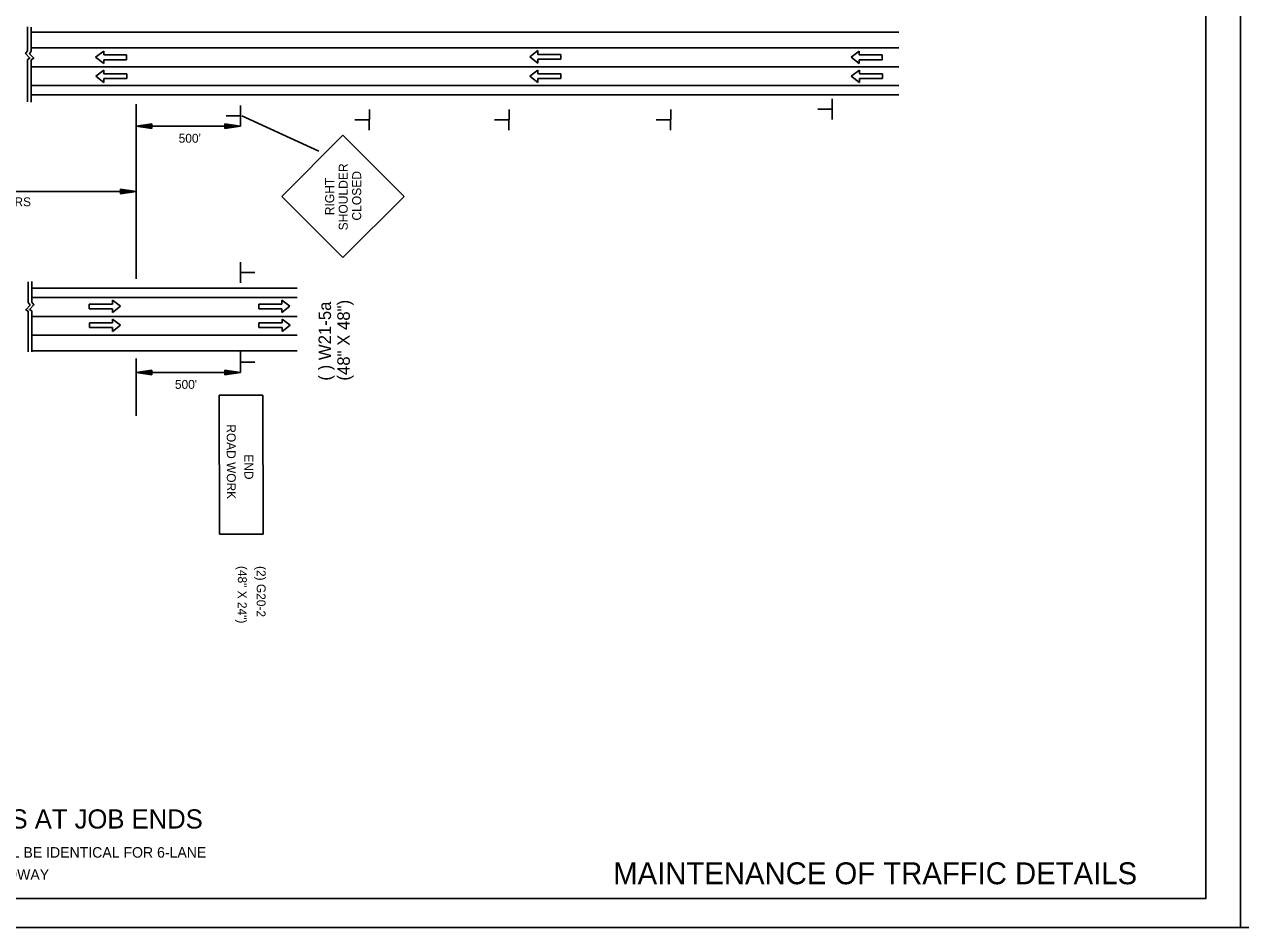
# Model space of a CAD drawing. Extents: x 1397271 to 1411271, y 376395 to 377888.
# Drawn here: x 1398438 to 1399604, y 376395 to 377260 of the extents above; entities that cross this region are included whole.
import ezdxf

# ---------------------------------------------------------------- set-up
doc = ezdxf.new("R2010")
doc.units = 0
for name, color, linetype in [('Default', 7, 'Continuous'), ('R_Border', 7, 'Continuous'), ('R_Draft', 7, 'Continuous'), ('R_MOT', 7, 'Continuous'), ('R_No Plot', 7, 'Continuous')]:
    doc.layers.add(name, color=color, linetype=linetype)

msp = doc.modelspace()

# ---------------------------------------------------------------- linework, layer by layer
at = {"layer": 'Default'}
for p, q in [((1398440.9, 377258), (1398440.9, 377235)), ((1398444.5, 377257.7), (1398444.5, 377234.7)), ((1399276.4, 377252.8), (1398445.2, 377252.8)), ((1399276.4, 377237.8), (1398445.2, 377237.8)), ((1398506.2, 377228.8), (1398514, 377234.8)), ((1398514, 377231), (1398514, 377234.8)), ((1398514, 377231), (1398536, 377231)), ((1398536, 377226.5), (1398536, 377231)), ((1398922.5, 377229.2), (1398930.2, 377235.2)), ((1398930.2, 377231.4), (1398930.2, 377235.2)), ((1398930.2, 377231.4), (1398952.3, 377231.4)), ((1398952.3, 377226.9), (1398952.3, 377231.4)), ((1399230.8, 377228.8), (1399238.5, 377234.8)), ((1399238.5, 377231), (1399238.5, 377234.8)), ((1399238.5, 377231), (1399260.6, 377231)), ((1399260.6, 377226.5), (1399260.6, 377231)), ((1398440.9, 377226.7), (1398440.9, 377186.1)), ((1398444.5, 377226.5), (1398444.5, 377185.9)), ((1399276.4, 377219.8), (1398445.2, 377219.8)), ((1398514, 377222.8), (1398506.2, 377228.8)), ((1398514, 377226.5), (1398536, 377226.5)), ((1398514, 377222.8), (1398514, 377226.5)), ((1398930.2, 377223.2), (1398922.5, 377229.2)), ((1398930.2, 377226.9), (1398952.3, 377226.9)), ((1398930.2, 377223.2), (1398930.2, 377226.9)), ((1399238.5, 377222.8), (1399230.8, 377228.8)), ((1399238.5, 377226.5), (1399260.6, 377226.5)), ((1399238.5, 377222.8), (1399238.5, 377226.5)), ((1398506.3, 377210.6), (1398514.1, 377216.6)), ((1398514.1, 377204.6), (1398506.3, 377210.6)), ((1398514.1, 377212.9), (1398514.1, 377216.6)), ((1398514.1, 377212.9), (1398536.1, 377212.9)), ((1398514.1, 377208.4), (1398536.1, 377208.4)), ((1398514.1, 377204.6), (1398514.1, 377208.4)), ((1398536.1, 377208.4), (1398536.1, 377212.9)), ((1398922.6, 377210.6), (1398930.4, 377216.6)), ((1398930.4, 377204.6), (1398922.6, 377210.6)), ((1398930.4, 377212.9), (1398930.4, 377216.6)), ((1398930.4, 377212.9), (1398952.4, 377212.9)), ((1398930.4, 377208.4), (1398952.4, 377208.4)), ((1398930.4, 377204.6), (1398930.4, 377208.4)), ((1398952.4, 377208.4), (1398952.4, 377212.9)), ((1399230.9, 377210.6), (1399238.7, 377216.6)), ((1399238.7, 377204.6), (1399230.9, 377210.6)), ((1399238.7, 377212.9), (1399238.7, 377216.6)), ((1399238.7, 377212.9), (1399260.7, 377212.9)), ((1399238.7, 377208.4), (1399260.7, 377208.4)), ((1399238.7, 377204.6), (1399238.7, 377208.4)), ((1399260.7, 377208.4), (1399260.7, 377212.9)), ((1399276.4, 377201.8), (1398445.2, 377201.8)), ((1399276.4, 377192.8), (1398445.2, 377192.8)), ((1398545.2, 377016.5), (1398545.2, 377183.8)), ((1398646.3, 377172.8), (1398720.3, 377138.8)), ((1398645.2, 377162.9), (1398545.2, 377162.9)), ((1398218.1, 377100.1), (1398545.2, 377100.1)), ((1398441.5, 377013.6), (1398441.5, 376993.7)), ((1398445.2, 377013.9), (1398445.2, 376994)), ((1398699.5, 377007.5), (1398445.2, 377007.5)), ((1398699.5, 376998.5), (1398445.2, 376998.5)), ((1398441.5, 376985.5), (1398441.5, 376946.4)), ((1398445.2, 376985.7), (1398445.2, 376946.4)), ((1398522.3, 376992.3), (1398500.2, 376992.3)), ((1398500.2, 376992.3), (1398500.2, 376987.8)), ((1398522.3, 376987.8), (1398500.2, 376987.8)), ((1398522.3, 376996.1), (1398522.3, 376992.3)), ((1398522.3, 376996.1), (1398530.1, 376990.1)), ((1398530.1, 376990.1), (1398522.3, 376984.1)), ((1398522.3, 376987.8), (1398522.3, 376984.1)), ((1398684.8, 376992.3), (1398662.8, 376992.3)), ((1398662.8, 376992.3), (1398662.8, 376987.8)), ((1398684.8, 376987.8), (1398662.8, 376987.8)), ((1398684.8, 376996.1), (1398684.8, 376992.3)), ((1398684.8, 376996.1), (1398692.6, 376990.1)), ((1398692.6, 376990.1), (1398684.8, 376984.1)), ((1398684.8, 376987.8), (1398684.8, 376984.1)), ((1398699.5, 376980.5), (1398445.2, 376980.5)), ((1398522.4, 376974.2), (1398500.3, 376974.2)), ((1398500.3, 376974.2), (1398500.3, 376969.7)), ((1398522.4, 376977.9), (1398522.4, 376974.2)), ((1398522.4, 376977.9), (1398530.2, 376971.9)), ((1398685, 376974.2), (1398662.9, 376974.2)), ((1398662.9, 376974.2), (1398662.9, 376969.7)), ((1398685, 376977.9), (1398685, 376974.2)), ((1398685, 376977.9), (1398692.7, 376971.9)), ((1398699.5, 376962.5), (1398445.2, 376962.5)), ((1398522.4, 376969.7), (1398500.3, 376969.7)), ((1398530.2, 376971.9), (1398522.4, 376965.9)), ((1398522.4, 376969.7), (1398522.4, 376965.9)), ((1398685, 376969.7), (1398662.9, 376969.7)), ((1398692.7, 376971.9), (1398685, 376965.9)), ((1398685, 376969.7), (1398685, 376965.9)), ((1398699.5, 376947.5), (1398445.2, 376947.5)), ((1398545.2, 376940.1), (1398545.2, 376885.1)), ((1398645.2, 376926.6), (1398545.2, 376926.6))]:
    msp.add_line(p, q, dxfattribs=at)
for points in [[(1398440.9, 377226.7), (1398443.2, 377228.1), (1398439.1, 377232.4), (1398440.9, 377235)], [(1398444.5, 377226.5), (1398446.9, 377227.9), (1398442.7, 377232.1), (1398444.5, 377234.7)], [(1398441.5, 376985.5), (1398439.2, 376986.9), (1398443.4, 376991.1), (1398441.5, 376993.7)], [(1398445.2, 376985.7), (1398442.8, 376987.1), (1398447, 376991.4), (1398445.2, 376994)]]:
    msp.add_lwpolyline(points, dxfattribs=at)
at = {"layer": 'R_Border'}
for q in [(1399571, 377860.7), (1397357.7, 376422.5)]:
    msp.add_line((1399571, 376422.5), q, dxfattribs=at)
at = {"layer": 'R_Draft'}
for p, q in [((1398560.2, 377165.1), (1398545.2, 377162.9)), ((1398560.2, 377160.6), (1398545.2, 377162.9)), ((1398560.2, 377164.8), (1398547.7, 377162.9)), ((1398560.2, 377161), (1398547.7, 377162.9)), ((1398560.2, 377164.4), (1398550.3, 377162.9)), ((1398560.2, 377161.4), (1398550.3, 377162.9)), ((1398560.2, 377164), (1398552.8, 377162.9)), ((1398560.2, 377161.8), (1398552.8, 377162.9)), ((1398560.2, 377163.6), (1398555.3, 377162.9)), ((1398560.2, 377162.2), (1398555.3, 377162.9)), ((1398560.2, 377163.2), (1398557.8, 377162.9)), ((1398560.2, 377162.5), (1398557.8, 377162.9)), ((1398560.2, 377160.6), (1398560.2, 377165.1)), ((1398630.2, 377165.1), (1398645.2, 377162.9)), ((1398630.2, 377165.1), (1398630.2, 377160.6)), ((1398630.2, 377164.8), (1398642.7, 377162.9)), ((1398630.2, 377164.4), (1398640.1, 377162.9)), ((1398630.2, 377164), (1398637.6, 377162.9)), ((1398630.2, 377163.6), (1398635.1, 377162.9)), ((1398630.2, 377163.2), (1398632.5, 377162.9)), ((1398630.2, 377160.6), (1398645.2, 377162.9)), ((1398630.2, 377162.2), (1398635.1, 377162.9)), ((1398630.2, 377161.4), (1398640.1, 377162.9)), ((1398630.2, 377161), (1398642.7, 377162.9)), ((1398630.2, 377161.8), (1398637.6, 377162.9)), ((1398630.2, 377162.5), (1398632.5, 377162.9)), ((1398530.2, 377102.4), (1398545.2, 377100.1)), ((1398530.2, 377102.4), (1398530.2, 377097.9)), ((1398530.2, 377102), (1398542.6, 377100.1)), ((1398530.2, 377101.6), (1398540.1, 377100.1)), ((1398530.2, 377101.3), (1398537.6, 377100.1)), ((1398530.2, 377100.9), (1398535, 377100.1)), ((1398530.2, 377100.5), (1398532.5, 377100.1)), ((1398530.2, 377097.9), (1398545.2, 377100.1)), ((1398530.2, 377099.4), (1398535, 377100.1)), ((1398530.2, 377098.6), (1398540.1, 377100.1)), ((1398530.2, 377098.3), (1398542.6, 377100.1)), ((1398530.2, 377099), (1398537.6, 377100.1)), ((1398530.2, 377099.8), (1398532.5, 377100.1)), ((1398560.2, 376928.8), (1398545.2, 376926.6)), ((1398560.2, 376928.5), (1398547.7, 376926.6)), ((1398560.2, 376928.1), (1398550.2, 376926.6)), ((1398560.2, 376927.7), (1398552.7, 376926.6)), ((1398560.2, 376927.3), (1398555.3, 376926.6)), ((1398560.2, 376924.3), (1398560.2, 376928.8)), ((1398630.2, 376928.8), (1398645.2, 376926.6)), ((1398630.2, 376928.8), (1398630.2, 376924.3)), ((1398630.2, 376928.5), (1398642.7, 376926.6)), ((1398630.2, 376928.1), (1398640.1, 376926.6)), ((1398630.2, 376927.7), (1398637.6, 376926.6)), ((1398630.2, 376927.3), (1398635, 376926.6)), ((1398560.2, 376924.3), (1398545.2, 376926.6)), ((1398560.2, 376924.7), (1398547.7, 376926.6)), ((1398560.2, 376925.1), (1398550.2, 376926.6)), ((1398560.2, 376925.5), (1398552.7, 376926.6)), ((1398560.2, 376925.9), (1398555.3, 376926.6)), ((1398560.2, 376927), (1398557.8, 376926.6)), ((1398560.2, 376926.2), (1398557.8, 376926.6)), ((1398630.2, 376927), (1398632.5, 376926.6)), ((1398630.2, 376924.3), (1398645.2, 376926.6)), ((1398630.2, 376925.9), (1398635, 376926.6)), ((1398630.2, 376925.1), (1398640.1, 376926.6)), ((1398630.2, 376924.7), (1398642.7, 376926.6)), ((1398630.2, 376925.5), (1398637.6, 376926.6)), ((1398630.2, 376926.2), (1398632.5, 376926.6))]:
    msp.add_line(p, q, dxfattribs=at)
at = {"layer": 'R_MOT'}
for p, q in [((1399212.6, 377169.2), (1399212.7, 377189.1)), ((1398645.2, 377172.8), (1398631.4, 377172.8)), ((1398645.2, 377162.9), (1398645.3, 377182.7)), ((1398768.7, 377158.9), (1398768.8, 377178.7)), ((1398902.6, 377158.8), (1398902.7, 377178.7)), ((1399057.6, 377158.8), (1399057.7, 377178.7)), ((1399212.6, 377179.1), (1399198.8, 377179.2)), ((1398768.8, 377168.7), (1398754.9, 377168.8)), ((1398902.6, 377168.7), (1398888.8, 377168.8)), ((1399057.6, 377168.7), (1399043.8, 377168.8)), ((1398743.4, 377154.1), (1398684.7, 377095.5)), ((1398743.4, 377154.1), (1398802, 377095.5)), ((1398684.7, 377095.5), (1398743.4, 377036.8)), ((1398802, 377095.5), (1398743.4, 377036.8)), ((1398645.2, 377032.4), (1398645.1, 377012.6)), ((1398645.1, 377022.6), (1398659, 377022.5)), ((1398645.2, 376926.6), (1398645.1, 376946.5)), ((1398645.1, 376936.5), (1398659, 376936.5)), ((1398624.9, 376771.6), (1398624.6, 376905.1)), ((1398624.6, 376905.1), (1398666.6, 376905.1)), ((1398666.8, 376771.6), (1398666.6, 376905.1)), ((1398624.9, 376771.6), (1398666.8, 376771.6))]:
    msp.add_line(p, q, dxfattribs=at)
at = {"layer": 'R_No Plot'}
msp.add_line((1397270.9, 376394.6), (1399604.3, 376394.6), dxfattribs=at)
for points in [[(1397270.9, 377888), (1399604.3, 377888), (1399604.3, 376394.6), (1397270.9, 376394.6)], [(1399604.3, 377888), (1401937.7, 377888), (1401937.7, 376394.6), (1399604.3, 376394.6)], [(1398995.2, 377860.7), (1398995.2, 377791.6), (1399245.3, 377791.6), (1399245.3, 377771.1), (1399407.7, 377771.1), (1399407.7, 377600.8), (1399571, 377600.8), (1399571, 376422.5), (1397357.7, 376422.5), (1397357.7, 377860.7)]]:
    msp.add_lwpolyline(points, close=True, dxfattribs=at)

# ---------------------------------------------------------------- texts
at = {"layer": 'Default'}
for s, height, p in [("500'", 8.54, (1398585.9, 377146.9)), ('LANE CLOSURE TAPERS', 8.54, (1398307.2, 377086)), ("500'", 8.54, (1398582.3, 376911)), ('ADVANCE WARNING SIGNS AT JOB ENDS', 18.375, (1398113.4, 376489.6)), ('NOTE: ADVANCE WARNING SIGN PLACEMENT WILL BE IDENTICAL FOR 6-LANE', 10.087, (1398096, 376461.7)), ('SECTIONS OF ROADWAY', 10.087, (1398296.8, 376440.5))]:
    msp.add_text(s, height=height, dxfattribs=at).set_placement(p)
at = {"layer": 'R_Border'}
msp.add_text('MAINTENANCE OF TRAFFIC DETAILS', height=21, dxfattribs=at).set_placement((1399002.6, 376436.2))
at = {"layer": 'R_MOT'}
for s, height, rotation, p in [('SHOULDER', 8.64, 90, (1398748, 377062.9)), ('CLOSED', 8.64, 90.0006, (1398760.9, 377072.3)), ('RIGHT', 8.64, 90.0004, (1398735, 377077.4)), ('( ) W21-5a', 12, 90, (1398732, 376918.9)), ('(48" X 48")', 12, 90, (1398750, 376918.9)), ('ROAD WORK', 8.54, 270.0992, (1398632, 376877)), ('END', 8.54, 270.0992, (1398648.9, 376848.2)), ('(48" X 24")', 8.54, 269.7913, (1398642.7, 376741.3)), ('(2) G20-2', 8.54, 269.7913, (1398660.8, 376741.2))]:
    msp.add_text(s, height=height, rotation=rotation, dxfattribs=at).set_placement(p)

doc.saveas('drawing.dxf')
